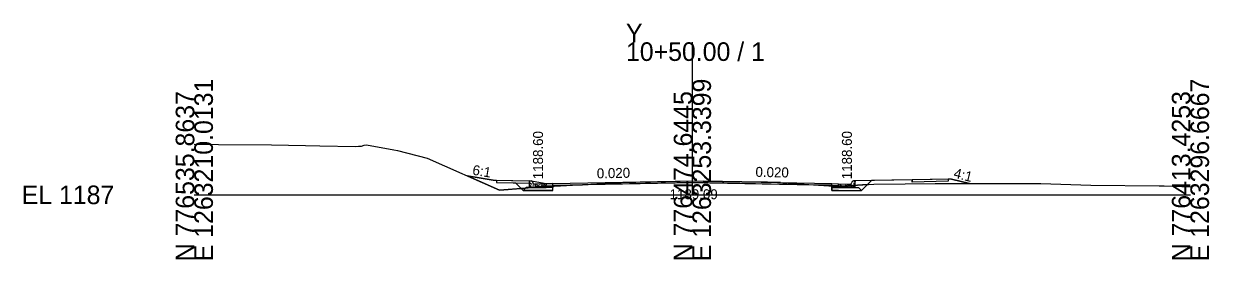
# Model space of a CAD drawing. Extents: x -51 to 1263719, y -10 to 776845.
# Drawn here: x -25.7 to 152.8, y 490.3 to 525.7 of the extents above; entities that cross this region are included whole.
import ezdxf

# ---------------------------------------------------------------- set-up
doc = ezdxf.new("R2010")
doc.units = 0
for name, color, linetype in [('Exist Cross Section Cell', 7, 'Continuous'), ('Exist XS Center Line Elevation Label', 7, 'Continuous'), ('Exist XS Ground Line', 7, 'Continuous'), ('Prop CMT Pvmt Course 1', 7, 'Continuous'), ('Prop CMT Pvmt Course 4', 7, 'Continuous'), ('Prop CMT Shld Paved Course 2', 7, 'Continuous'), ('Prop CMT Subgrade Earthwork', 7, 'Continuous'), ('Prop Conc 4in Sidewalk', 7, 'Continuous'), ('Prop XS Earthwork Shape', 7, 'Continuous'), ('Prop XS Elevation Labels', 7, 'Continuous'), ('Prop XS Finish Grade', 7, 'Continuous'), ('Prop XS SE Text', 7, 'Continuous'), ('Prop XS Side Slope Text', 7, 'Continuous'), ('Scratch_Level_0', 7, 'Continuous'), ('Typical Curb CELL', 7, 'Continuous')]:
    doc.layers.add(name, color=color, linetype=linetype)

msp = doc.modelspace()

# ---------------------------------------------------------------- linework, layer by layer
at = {"layer": 'Exist Cross Section Cell'}
for p, q in [((75, 500), (75, 522.95)), ((0, 500), (75, 500)), ((75, 500), (150, 500))]:
    msp.add_line(p, q, dxfattribs=at)
at = {"layer": 'Exist XS Ground Line'}
msp.add_lwpolyline([(0, 507.65), (3.66, 507.59), (11.64, 507.53), (16.74, 507.41), (18.9, 507.36), (24.25, 507.28), (24.71, 507.31), (25.15, 507.34), (25.59, 507.45), (25.93, 507.54), (30.04, 506.76), (30.6, 506.65), (35.04, 505.52), (45.96, 500.71), (49.84, 500.99), (52.19, 501.28), (53.21, 501.28), (55.14, 501.36), (64.28, 501.84), (75.37, 502.09), (81.12, 502.03), (86.32, 501.97), (87.08, 501.92), (97.11, 501.28), (99.84, 501.47), (102.31, 501.61), (107.06, 501.66), (111.55, 501.69), (121.27, 501.71), (127.46, 501.7), (135.01, 501.46), (145.3, 501.38), (145.63, 501.38), (146.05, 501.36), (150, 501.22)], dxfattribs=at)
at = {"layer": 'Prop CMT Pvmt Course 1'}
for p, q in [((53.98, 501.44), (53.98, 501.69)), ((96, 501.44), (96, 501.69)), ((52.98, 501.67), (52.98, 501.42)), ((53.98, 501.44), (52.98, 501.42)), ((96, 501.44), (97, 501.42)), ((97, 501.67), (97, 501.42))]:
    msp.add_line(p, q, dxfattribs=at)
msp.add_lwpolyline([(53.98, 501.44), (75, 501.86), (96, 501.44)], dxfattribs=at)
at = {"layer": 'Prop CMT Pvmt Course 4'}
for p, q in [((49.98, 501.09), (49.52, 500.63)), ((52.98, 500.63), (49.52, 500.63)), ((52.98, 501.09), (49.98, 501.09)), ((53.98, 500.65), (52.98, 500.63)), ((53.98, 500.65), (53.98, 501.11)), ((96, 500.65), (96, 501.11)), ((96, 500.65), (97, 500.63)), ((97, 501.09), (100, 501.09)), ((97, 500.63), (100.46, 500.63)), ((100, 501.09), (100.46, 500.63))]:
    msp.add_line(p, q, dxfattribs=at)
at = {"layer": 'Prop CMT Shld Paved Course 2'}
for p, q in [((52.98, 501.09), (52.98, 501.42)), ((53.98, 501.11), (52.98, 501.09)), ((53.98, 501.11), (53.98, 501.44)), ((96, 501.11), (96, 501.44)), ((96, 501.11), (97, 501.09)), ((97, 501.09), (97, 501.42))]:
    msp.add_line(p, q, dxfattribs=at)
at = {"layer": 'Prop CMT Subgrade Earthwork'}
for p, q in [((49.52, 500.63), (48.35, 501.8)), ((100.46, 500.63), (101.97, 502.14)), ((52.98, 500.63), (49.52, 500.63)), ((52.98, 500.63), (53.98, 500.65)), ((53.98, 500.65), (53.98, 501.31)), ((96, 500.65), (96, 501.35)), ((97, 500.63), (96, 500.65)), ((97, 500.63), (100.46, 500.63))]:
    msp.add_line(p, q, dxfattribs=at)
at = {"layer": 'Prop Conc 4in Sidewalk'}
for p, q in [((45.48, 502.19), (50.48, 502.09)), ((45.48, 502.19), (45.48, 501.86)), ((45.48, 501.86), (50.48, 501.76)), ((50.48, 501.76), (50.48, 502.09)), ((113.5, 502.37), (108.1, 502.26)), ((108.1, 502.26), (108.1, 501.93)), ((113.5, 502.04), (108.1, 501.93)), ((113.5, 502.37), (113.5, 502.04))]:
    msp.add_line(p, q, dxfattribs=at)
at = {"layer": 'Prop XS Earthwork Shape'}
for points in [[(45.48, 502.19), (45.48, 501.86), (48.35, 501.8), (49.2, 500.95), (45.96, 500.71), (41.11, 502.85), (44.98, 502.2)], [(64.28, 501.84), (75.37, 502.09), (76.61, 502.08), (88.29, 501.85), (93.98, 501.48), (75, 501.86), (58.46, 501.53)], [(81.12, 502.03), (86.32, 501.97), (87.08, 501.92), (88.29, 501.85), (76.61, 502.08)], [(113.5, 502.04), (108.1, 501.93), (108.1, 502.26), (101.97, 502.14), (101.39, 501.56), (102.31, 501.61), (107.06, 501.66), (111.55, 501.69), (116.72, 501.7), (114, 502.38), (113.5, 502.37)], [(53.98, 500.65), (53.98, 501.11), (52.98, 501.09), (52.98, 501.28), (52.19, 501.28), (49.84, 500.99), (49.2, 500.95), (49.52, 500.63), (52.98, 500.63)], [(53.98, 501.11), (52.98, 501.09), (52.98, 501.28), (53.21, 501.28), (53.98, 501.31)], [(53.98, 501.44), (58.46, 501.53), (55.14, 501.36), (53.98, 501.31)], [(96, 501.35), (96, 501.44), (93.98, 501.48)], [(100.46, 500.63), (101.39, 501.56), (99.84, 501.47), (97.11, 501.28), (97, 501.29), (97, 501.09), (96, 501.11), (96, 500.65), (97, 500.63)], [(96, 501.11), (96, 501.35), (97, 501.29), (97, 501.09)]]:
    msp.add_lwpolyline(points, close=True, dxfattribs=at)
at = {"layer": 'Prop XS Finish Grade'}
for p, q in [((44.98, 502.2), (41.11, 502.85)), ((44.98, 502.2), (50.48, 502.09)), ((53.98, 501.69), (52.98, 501.67)), ((96, 501.69), (97, 501.67)), ((114, 502.38), (99.5, 502.09)), ((114, 502.38), (116.72, 501.7))]:
    msp.add_line(p, q, dxfattribs=at)
msp.add_lwpolyline([(53.98, 501.69), (75, 502.11), (96, 501.69)], dxfattribs=at)
at = {"layer": 'Scratch_Level_0'}
msp.add_line((52.98, 501.67), (50.48, 502.09), dxfattribs=at)
at = {"layer": 'Typical Curb CELL'}
for p, q in [((50.48, 501.09), (50.48, 502.09)), ((50.48, 502.09), (50.74, 502.09)), ((50.51, 501.71), (50.67, 501.76)), ((50.65, 501.67), (50.51, 501.71)), ((50.67, 501.76), (50.65, 501.67)), ((50.98, 501.84), (50.98, 501.85)), ((99, 501.84), (99, 501.85)), ((99.5, 502.09), (99.24, 502.09)), ((99.31, 501.76), (99.33, 501.67)), ((99.46, 501.71), (99.31, 501.76)), ((99.33, 501.67), (99.46, 501.71)), ((99.5, 501.09), (99.5, 502.09)), ((50.48, 501.09), (52.98, 501.09)), ((50.64, 501.39), (50.54, 501.32)), ((50.54, 501.32), (50.7, 501.28)), ((50.7, 501.28), (50.64, 501.39)), ((52.98, 501.67), (51.23, 501.6)), ((51.38, 501.45), (51.35, 501.34)), ((51.35, 501.34), (51.47, 501.33)), ((51.47, 501.33), (51.38, 501.45)), ((51.89, 501.39), (51.78, 501.32)), ((51.78, 501.32), (51.95, 501.28)), ((51.95, 501.28), (51.89, 501.39)), ((52.63, 501.45), (52.59, 501.34)), ((52.59, 501.34), (52.72, 501.33)), ((52.72, 501.33), (52.63, 501.45)), ((52.98, 501.09), (52.98, 501.67)), ((97, 501.09), (97, 501.67)), ((97, 501.67), (98.75, 501.6)), ((99.5, 501.09), (97, 501.09)), ((97.26, 501.33), (97.35, 501.45)), ((97.38, 501.34), (97.26, 501.33)), ((97.35, 501.45), (97.38, 501.34)), ((98.03, 501.28), (98.09, 501.39)), ((98.19, 501.32), (98.03, 501.28)), ((98.09, 501.39), (98.19, 501.32)), ((98.51, 501.33), (98.6, 501.45)), ((98.63, 501.34), (98.51, 501.33)), ((98.6, 501.45), (98.63, 501.34)), ((99.27, 501.28), (99.34, 501.39)), ((99.44, 501.32), (99.27, 501.28)), ((99.34, 501.39), (99.44, 501.32))]:
    msp.add_line(p, q, dxfattribs=at)
for centre in [(50.49, 501.98), (50.54, 501.8), (50.71, 502.01), (99.27, 502.01), (99.43, 501.8), (99.49, 501.98), (50.62, 501.14), (50.64, 501.52), (50.76, 501.58), (50.79, 501.18), (50.94, 501.41), (50.97, 501.11), (51.02, 501.6), (51.03, 501.55), (51.03, 501.23), (51.06, 501.38), (51.14, 501.14), (51.21, 501.47), (51.24, 501.57), (51.35, 501.17), (51.43, 501.53), (51.51, 501.1), (51.53, 501.58), (51.56, 501.33), (51.64, 501.49), (51.65, 501.28), (51.69, 501.52), (51.71, 501.43), (51.72, 501.12), (51.87, 501.14), (51.89, 501.52), (52.01, 501.58), (52.04, 501.18), (52.18, 501.41), (52.22, 501.11), (52.26, 501.6), (52.28, 501.55), (52.28, 501.23), (52.31, 501.38), (52.39, 501.14), (52.46, 501.47), (52.49, 501.57), (52.6, 501.17), (52.64, 501.63), (52.68, 501.53), (52.76, 501.1), (52.78, 501.62), (52.81, 501.33), (52.89, 501.49), (52.9, 501.28), (52.94, 501.52), (52.96, 501.43), (52.97, 501.12), (97.01, 501.12), (97.02, 501.43), (97.03, 501.52), (97.07, 501.28), (97.09, 501.49), (97.17, 501.33), (97.2, 501.61), (97.22, 501.1), (97.3, 501.53), (97.34, 501.63), (97.38, 501.16), (97.49, 501.57), (97.52, 501.47), (97.59, 501.14), (97.67, 501.38), (97.69, 501.55), (97.7, 501.23), (97.71, 501.6), (97.76, 501.11), (97.79, 501.41), (97.93, 501.18), (97.97, 501.57), (98.09, 501.52), (98.11, 501.14), (98.26, 501.12), (98.27, 501.43), (98.28, 501.52), (98.32, 501.28), (98.34, 501.49), (98.42, 501.33), (98.45, 501.58), (98.47, 501.1), (98.54, 501.53), (98.63, 501.16), (98.74, 501.57), (98.77, 501.47), (98.84, 501.14), (98.92, 501.38), (98.94, 501.55), (98.95, 501.23), (98.96, 501.6), (99.01, 501.11), (99.04, 501.41), (99.18, 501.18), (99.22, 501.57), (99.34, 501.52), (99.35, 501.14)]:
    msp.add_circle(centre, 0.00802, dxfattribs=at)
for centre, start, end in [((50.74, 501.85), 0, 90), ((51.22, 501.84), 180, 272.3845), ((98.76, 501.84), 267.6155, 0), ((99.24, 501.85), 90, 180)]:
    msp.add_arc(centre, 0.24, start, end, dxfattribs=at)

# ---------------------------------------------------------------- texts
at = {"layer": 'Exist Cross Section Cell'}
for s, p in [('Y', (65, 522.95)), ('10+50.00 / 1', (65, 520.15)), ('EL 1187', (-26, 498.6))]:
    msp.add_text(s, height=2.8, dxfattribs=at).set_placement(p)
for s, p in [('E 1263210.0131', (2.8, 490)), ('E 1263253.3399', (77.8, 490)), ('E 1263296.6667', (152.8, 490)), ('N 776535.8637', (0, 490)), ('N 776474.6445', (75, 490)), ('N 776413.4253', (150, 490))]:
    msp.add_text(s, height=2.8, rotation=90, dxfattribs=at).set_placement(p)
at = {"layer": 'Exist XS Center Line Elevation Label'}
msp.add_text('1189.09', height=1.5, dxfattribs=at).set_placement((71.57, 499.34))
at = {"layer": 'Prop XS Elevation Labels'}
for p in [(52.51, 502.35), (99.02, 502.35)]:
    msp.add_text('1188.60', height=1.5, rotation=90, dxfattribs=at).set_placement(p)
at = {"layer": 'Prop XS SE Text'}
for rotation, p in [(1.1458, (60.62, 502.48)), (358.8542, (84.49, 502.71))]:
    msp.add_text('0.020', height=1.5, rotation=rotation, dxfattribs=at).set_placement(p)
at = {"layer": 'Prop XS Side Slope Text'}
for s, rotation, p in [('6:1', 350.5377, (41.8, 503.05)), ('4:1', 345.9638, (114.25, 502.6))]:
    msp.add_text(s, height=1.5, rotation=rotation, dxfattribs=at).set_placement(p)

doc.saveas('drawing.dxf')
